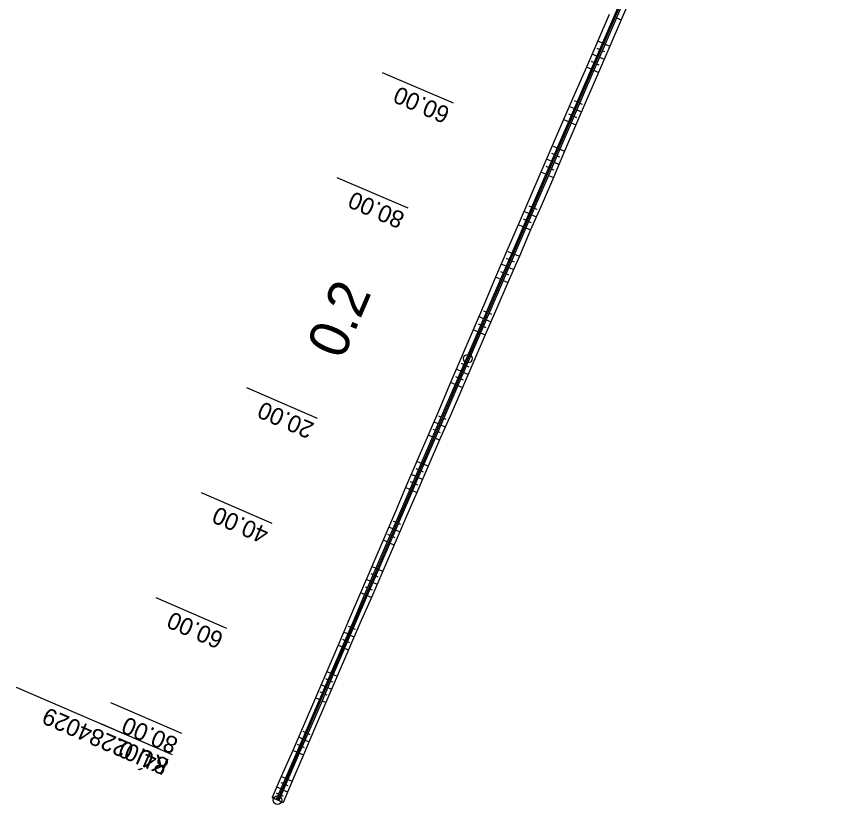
# Model space of a CAD drawing. Extents: x -481685 to -479315, y -1112639 to -1112242.
# Drawn here: x -480665.3 to -480519.8, y -1112634.9 to -1112497.2 of the extents above; entities that cross this region are included whole.
import ezdxf

# ---------------------------------------------------------------- set-up
doc = ezdxf.new("R2010")
doc.units = 0
for name, color, linetype in [('O6_HATCH_SLOPE_L', 7, 'Continuous'), ('O6_HATCH_SLOPE_R', 7, 'Continuous'), ('O6_HECTOMETRY', 7, 'Continuous'), ('O6_HLBODY', 7, 'Continuous'), ('O6_HRANA_TELESO', 7, 'Continuous'), ('O6_OSA', 7, 'Continuous'), ('O6_STANICENI', 7, 'Continuous'), ('O6_VOZOVKA', 7, 'Continuous'), ('O6_ZPEVKRAJ', 7, 'Continuous')]:
    doc.layers.add(name, color=color, linetype=linetype)

msp = doc.modelspace()

# ---------------------------------------------------------------- linework, layer by layer
at = {"layer": 'O6_HATCH_SLOPE_L'}
for p, q in [((-480560.38, -1112497.36), (-480559.57, -1112497.71)), ((-480562.86, -1112503.1), (-480562.45, -1112503.27)), ((-480562.04, -1112503.45), (-480562.04, -1112503.45)), ((-480563.35, -1112504.25), (-480562.53, -1112504.6)), ((-480564.34, -1112506.54), (-480563.52, -1112506.9)), ((-480563.85, -1112505.39), (-480563.43, -1112505.57)), ((-480563.02, -1112505.75), (-480563.02, -1112505.75)), ((-480566.82, -1112512.28), (-480566.4, -1112512.46)), ((-480567.31, -1112513.43), (-480566.48, -1112513.79)), ((-480565.98, -1112512.64), (-480565.98, -1112512.64)), ((-480567.81, -1112514.58), (-480567.39, -1112514.76)), ((-480566.97, -1112514.94), (-480566.97, -1112514.94)), ((-480568.3, -1112515.72), (-480567.46, -1112516.08)), ((-480571.27, -1112522.61), (-480570.42, -1112522.98)), ((-480570.78, -1112521.46), (-480570.35, -1112521.64)), ((-480569.93, -1112521.83), (-480569.93, -1112521.83)), ((-480571.77, -1112523.76), (-480571.34, -1112523.94)), ((-480570.92, -1112524.12), (-480570.92, -1112524.12)), ((-480572.26, -1112524.91), (-480571.41, -1112525.27)), ((-480574.74, -1112530.65), (-480574.31, -1112530.83)), ((-480573.89, -1112531.01), (-480573.89, -1112531.01)), ((-480575.73, -1112532.94), (-480575.3, -1112533.12)), ((-480575.23, -1112531.79), (-480574.38, -1112532.16)), ((-480576.22, -1112534.09), (-480575.38, -1112534.45)), ((-480574.88, -1112533.31), (-480574.88, -1112533.31)), ((-480578.7, -1112539.83), (-480578.28, -1112540.01)), ((-480577.86, -1112540.19), (-480577.86, -1112540.19)), ((-480579.19, -1112540.98), (-480578.35, -1112541.34)), ((-480579.69, -1112542.12), (-480579.27, -1112542.3)), ((-480578.85, -1112542.48), (-480578.85, -1112542.48)), ((-480580.18, -1112543.27), (-480579.35, -1112543.63)), ((-480583.15, -1112550.16), (-480582.33, -1112550.51)), ((-480582.66, -1112549.01), (-480582.25, -1112549.19)), ((-480581.83, -1112549.36), (-480581.83, -1112549.36)), ((-480583.65, -1112551.3), (-480583.24, -1112551.48)), ((-480582.83, -1112551.66), (-480582.83, -1112551.66)), ((-480584.14, -1112552.45), (-480583.33, -1112552.8)), ((-480586.62, -1112558.19), (-480586.22, -1112558.36)), ((-480585.82, -1112558.53), (-480585.82, -1112558.53)), ((-480587.61, -1112560.49), (-480587.21, -1112560.66)), ((-480587.11, -1112559.34), (-480586.32, -1112559.68)), ((-480588.1, -1112561.64), (-480587.32, -1112561.97)), ((-480586.82, -1112560.83), (-480586.82, -1112560.83)), ((-480590.58, -1112567.37), (-480590.2, -1112567.54)), ((-480589.81, -1112567.71), (-480589.81, -1112567.71)), ((-480591.07, -1112568.52), (-480590.31, -1112568.85)), ((-480591.57, -1112569.67), (-480591.19, -1112569.83)), ((-480590.81, -1112570), (-480590.81, -1112570)), ((-480592.06, -1112570.82), (-480591.31, -1112571.14)), ((-480594.54, -1112576.56), (-480594.17, -1112576.72)), ((-480595.03, -1112577.7), (-480594.29, -1112578.02)), ((-480593.8, -1112576.88), (-480593.8, -1112576.88)), ((-480595.53, -1112578.85), (-480595.16, -1112579.01)), ((-480594.79, -1112579.17), (-480594.79, -1112579.17)), ((-480596.02, -1112580), (-480595.29, -1112580.32)), ((-480598.5, -1112585.74), (-480598.14, -1112585.9)), ((-480597.77, -1112586.05), (-480597.77, -1112586.05)), ((-480599.49, -1112588.03), (-480599.13, -1112588.19)), ((-480598.99, -1112586.89), (-480598.27, -1112587.2)), ((-480599.98, -1112589.18), (-480599.27, -1112589.49)), ((-480598.77, -1112588.35), (-480598.77, -1112588.35)), ((-480602.46, -1112594.92), (-480602.1, -1112595.07)), ((-480601.75, -1112595.23), (-480601.75, -1112595.23)), ((-480602.95, -1112596.07), (-480602.25, -1112596.37)), ((-480603.94, -1112598.36), (-480603.24, -1112598.67)), ((-480603.45, -1112597.22), (-480603.1, -1112597.37)), ((-480602.74, -1112597.52), (-480602.74, -1112597.52)), ((-480606.42, -1112604.1), (-480606.07, -1112604.25)), ((-480606.92, -1112605.25), (-480606.23, -1112605.55)), ((-480605.73, -1112604.4), (-480605.73, -1112604.4)), ((-480607.41, -1112606.4), (-480607.07, -1112606.55)), ((-480606.72, -1112606.7), (-480606.72, -1112606.7)), ((-480607.91, -1112607.55), (-480607.22, -1112607.84)), ((-480610.88, -1112614.43), (-480610.2, -1112614.73)), ((-480610.38, -1112613.29), (-480610.04, -1112613.43)), ((-480609.71, -1112613.58), (-480609.71, -1112613.58)), ((-480611.37, -1112615.58), (-480611.03, -1112615.73)), ((-480610.7, -1112615.87), (-480610.7, -1112615.87)), ((-480611.86, -1112616.73), (-480611.19, -1112617.02)), ((-480614.34, -1112622.47), (-480613.99, -1112622.62)), ((-480613.65, -1112622.77), (-480613.65, -1112622.77)), ((-480614.84, -1112623.62), (-480614.14, -1112623.92)), ((-480615.83, -1112625.91), (-480615.12, -1112626.22)), ((-480615.33, -1112624.76), (-480614.98, -1112624.91)), ((-480614.63, -1112625.06), (-480614.63, -1112625.06)), ((-480618.2, -1112631.43), (-480617.84, -1112631.58)), ((-480617.48, -1112631.74), (-480617.48, -1112631.74)), ((-480619, -1112633.27), (-480618.64, -1112633.43)), ((-480618.6, -1112632.35), (-480617.88, -1112632.66)), ((-480619.4, -1112634.19), (-480618.67, -1112634.51)), ((-480618.27, -1112633.58), (-480618.27, -1112633.58))]:
    msp.add_line(p, q, dxfattribs=at)
at = {"layer": 'O6_HATCH_SLOPE_R'}
for p, q in [((-480563.83, -1112504.04), (-480564.65, -1112503.69)), ((-480564.15, -1112502.54), (-480564.15, -1112502.54)), ((-480563.33, -1112502.89), (-480563.74, -1112502.72)), ((-480565.15, -1112504.83), (-480565.15, -1112504.83)), ((-480564.32, -1112505.19), (-480564.73, -1112505.01)), ((-480564.82, -1112506.33), (-480565.64, -1112505.98)), ((-480568.13, -1112511.72), (-480568.13, -1112511.72)), ((-480567.29, -1112512.07), (-480567.71, -1112511.89)), ((-480569.12, -1112514.01), (-480569.12, -1112514.01)), ((-480567.79, -1112513.22), (-480568.62, -1112512.86)), ((-480568.78, -1112515.52), (-480569.62, -1112515.16)), ((-480568.28, -1112514.37), (-480568.7, -1112514.19)), ((-480572.1, -1112520.89), (-480572.1, -1112520.89)), ((-480571.25, -1112521.26), (-480571.68, -1112521.07)), ((-480571.75, -1112522.4), (-480572.6, -1112522.04)), ((-480573.09, -1112523.19), (-480573.09, -1112523.19)), ((-480572.24, -1112523.55), (-480572.67, -1112523.37)), ((-480572.74, -1112524.7), (-480573.59, -1112524.33)), ((-480575.71, -1112531.59), (-480576.56, -1112531.22)), ((-480576.07, -1112530.07), (-480576.07, -1112530.07)), ((-480575.22, -1112530.44), (-480575.64, -1112530.26)), ((-480577.05, -1112532.37), (-480577.05, -1112532.37)), ((-480576.21, -1112532.73), (-480576.63, -1112532.55)), ((-480576.7, -1112533.88), (-480577.55, -1112533.52)), ((-480580.02, -1112539.26), (-480580.02, -1112539.26)), ((-480579.17, -1112539.62), (-480579.6, -1112539.44)), ((-480581, -1112541.56), (-480581, -1112541.56)), ((-480579.67, -1112540.77), (-480580.51, -1112540.41)), ((-480580.66, -1112543.06), (-480581.5, -1112542.7)), ((-480580.17, -1112541.92), (-480580.58, -1112541.74)), ((-480583.96, -1112548.45), (-480583.96, -1112548.45)), ((-480583.14, -1112548.8), (-480583.55, -1112548.63)), ((-480583.63, -1112549.95), (-480584.45, -1112549.6)), ((-480584.94, -1112550.75), (-480584.94, -1112550.75)), ((-480584.12, -1112551.1), (-480584.53, -1112550.92)), ((-480584.62, -1112552.25), (-480585.43, -1112551.9)), ((-480587.89, -1112557.64), (-480587.89, -1112557.64)), ((-480587.59, -1112559.13), (-480588.38, -1112558.79)), ((-480587.1, -1112557.99), (-480587.49, -1112557.81)), ((-480588.88, -1112559.94), (-480588.88, -1112559.94)), ((-480588.09, -1112560.28), (-480588.48, -1112560.11)), ((-480588.58, -1112561.43), (-480589.37, -1112561.09)), ((-480591.82, -1112566.84), (-480591.82, -1112566.84)), ((-480591.06, -1112567.17), (-480591.44, -1112567)), ((-480592.81, -1112569.14), (-480592.81, -1112569.14)), ((-480592.05, -1112569.46), (-480592.43, -1112569.3)), ((-480591.55, -1112568.32), (-480592.31, -1112567.99)), ((-480592.54, -1112570.61), (-480593.3, -1112570.29)), ((-480595.76, -1112576.03), (-480595.76, -1112576.03)), ((-480595.02, -1112576.35), (-480595.39, -1112576.19)), ((-480595.51, -1112577.5), (-480596.25, -1112577.18)), ((-480596.5, -1112579.79), (-480597.24, -1112579.48)), ((-480596.75, -1112578.33), (-480596.75, -1112578.33)), ((-480596.01, -1112578.65), (-480596.38, -1112578.49)), ((-480599.7, -1112585.22), (-480599.7, -1112585.22)), ((-480599.47, -1112586.68), (-480600.2, -1112586.37)), ((-480598.98, -1112585.53), (-480599.34, -1112585.38)), ((-480600.69, -1112587.52), (-480600.69, -1112587.52)), ((-480599.97, -1112587.83), (-480600.33, -1112587.67)), ((-480600.46, -1112588.98), (-480601.18, -1112588.67)), ((-480603.65, -1112594.41), (-480603.65, -1112594.41)), ((-480602.94, -1112594.72), (-480603.29, -1112594.56)), ((-480604.63, -1112596.71), (-480604.63, -1112596.71)), ((-480603.93, -1112597.01), (-480604.28, -1112596.86)), ((-480603.43, -1112595.86), (-480604.14, -1112595.56)), ((-480604.42, -1112598.16), (-480605.13, -1112597.85)), ((-480607.59, -1112603.6), (-480607.59, -1112603.6)), ((-480606.9, -1112603.9), (-480607.24, -1112603.75)), ((-480607.39, -1112605.05), (-480608.08, -1112604.75)), ((-480608.38, -1112607.34), (-480609.07, -1112607.05)), ((-480608.58, -1112605.9), (-480608.58, -1112605.9)), ((-480607.89, -1112606.19), (-480608.23, -1112606.04)), ((-480611.53, -1112612.79), (-480611.53, -1112612.79)), ((-480610.86, -1112613.08), (-480611.19, -1112612.93)), ((-480611.35, -1112614.23), (-480612.02, -1112613.94)), ((-480612.52, -1112615.09), (-480612.52, -1112615.09)), ((-480611.85, -1112615.38), (-480612.18, -1112615.23)), ((-480612.34, -1112616.52), (-480613.01, -1112616.24)), ((-480615.31, -1112623.41), (-480615.99, -1112623.12)), ((-480615.49, -1112621.97), (-480615.49, -1112621.97)), ((-480614.82, -1112622.26), (-480615.16, -1112622.12)), ((-480616.49, -1112624.26), (-480616.49, -1112624.26)), ((-480615.81, -1112624.56), (-480616.15, -1112624.41)), ((-480616.3, -1112625.71), (-480616.99, -1112625.41)), ((-480619.08, -1112632.14), (-480619.79, -1112631.84)), ((-480619.39, -1112630.92), (-480619.39, -1112630.92)), ((-480618.68, -1112631.22), (-480619.03, -1112631.07)), ((-480620.19, -1112632.76), (-480620.19, -1112632.76)), ((-480619.48, -1112633.07), (-480619.83, -1112632.91)), ((-480619.88, -1112633.99), (-480620.59, -1112633.68))]:
    msp.add_line(p, q, dxfattribs=at)
at = {"layer": 'O6_HECTOMETRY'}
msp.add_circle((-480586.36, -1112556.94), 0.75, dxfattribs=at)
at = {"layer": 'O6_HLBODY'}
msp.add_line((-480638.01, -1112626.18), (-480665.28, -1112614.42), dxfattribs=at)
msp.add_circle((-480619.64, -1112634.1), 0.75, dxfattribs=at)
at = {"layer": 'O6_HRANA_TELESO'}
for p, q in [((-480557.6, -1112493.11), (-480559.57, -1112497.71)), ((-480561.67, -1112496.8), (-480563.66, -1112501.39)), ((-480559.57, -1112497.71), (-480561.54, -1112502.3)), ((-480563.66, -1112501.39), (-480565.64, -1112505.98)), ((-480561.54, -1112502.3), (-480563.52, -1112506.9)), ((-480565.64, -1112505.98), (-480567.63, -1112510.57)), ((-480563.52, -1112506.9), (-480565.49, -1112511.49)), ((-480567.63, -1112510.57), (-480569.62, -1112515.16)), ((-480565.49, -1112511.49), (-480567.46, -1112516.08)), ((-480569.62, -1112515.16), (-480571.6, -1112519.74)), ((-480567.46, -1112516.08), (-480569.44, -1112520.68)), ((-480571.6, -1112519.74), (-480573.59, -1112524.33)), ((-480569.44, -1112520.68), (-480571.41, -1112525.27)), ((-480573.59, -1112524.33), (-480575.57, -1112528.92)), ((-480571.41, -1112525.27), (-480573.39, -1112529.86)), ((-480575.57, -1112528.92), (-480577.55, -1112533.52)), ((-480573.39, -1112529.86), (-480575.38, -1112534.45)), ((-480577.55, -1112533.52), (-480579.52, -1112538.11)), ((-480575.38, -1112534.45), (-480577.36, -1112539.04)), ((-480579.52, -1112538.11), (-480581.5, -1112542.7)), ((-480577.36, -1112539.04), (-480579.35, -1112543.63)), ((-480581.5, -1112542.7), (-480583.47, -1112547.3)), ((-480579.35, -1112543.63), (-480581.34, -1112548.22)), ((-480583.47, -1112547.3), (-480585.43, -1112551.9)), ((-480581.34, -1112548.22), (-480583.33, -1112552.8)), ((-480585.43, -1112551.9), (-480587.4, -1112556.49)), ((-480583.33, -1112552.8), (-480585.32, -1112557.39)), ((-480587.4, -1112556.49), (-480589.37, -1112561.09)), ((-480585.32, -1112557.39), (-480587.32, -1112561.97)), ((-480589.37, -1112561.09), (-480591.33, -1112565.69)), ((-480587.32, -1112561.97), (-480589.31, -1112566.56)), ((-480591.33, -1112565.69), (-480593.3, -1112570.29)), ((-480589.31, -1112566.56), (-480591.31, -1112571.14)), ((-480593.3, -1112570.29), (-480595.27, -1112574.88)), ((-480591.31, -1112571.14), (-480593.3, -1112575.73)), ((-480595.27, -1112574.88), (-480597.24, -1112579.48)), ((-480593.3, -1112575.73), (-480595.29, -1112580.32)), ((-480597.24, -1112579.48), (-480599.21, -1112584.07)), ((-480595.29, -1112580.32), (-480597.28, -1112584.91)), ((-480599.21, -1112584.07), (-480601.18, -1112588.67)), ((-480597.28, -1112584.91), (-480599.27, -1112589.49)), ((-480601.18, -1112588.67), (-480603.15, -1112593.26)), ((-480599.27, -1112589.49), (-480601.25, -1112594.08)), ((-480603.15, -1112593.26), (-480605.13, -1112597.85)), ((-480601.25, -1112594.08), (-480603.24, -1112598.67)), ((-480605.13, -1112597.85), (-480607.1, -1112602.45)), ((-480603.24, -1112598.67), (-480605.23, -1112603.26)), ((-480607.1, -1112602.45), (-480609.07, -1112607.05)), ((-480605.23, -1112603.26), (-480607.22, -1112607.84)), ((-480609.07, -1112607.05), (-480611.04, -1112611.64)), ((-480607.22, -1112607.84), (-480609.21, -1112612.43)), ((-480611.04, -1112611.64), (-480613.01, -1112616.24)), ((-480609.21, -1112612.43), (-480611.19, -1112617.02)), ((-480613.01, -1112616.24), (-480615, -1112620.82)), ((-480611.19, -1112617.02), (-480613.16, -1112621.62)), ((-480615, -1112620.82), (-480616.99, -1112625.41)), ((-480613.16, -1112621.62), (-480615.12, -1112626.22)), ((-480616.99, -1112625.41), (-480618.99, -1112629.99)), ((-480615.12, -1112626.22), (-480617.09, -1112630.81)), ((-480618.99, -1112629.99), (-480620.59, -1112633.68)), ((-480617.09, -1112630.81), (-480618.67, -1112634.51))]:
    msp.add_line(p, q, dxfattribs=at)
at = {"layer": 'O6_OSA'}
msp.add_line((-480519.82, -1112402.65), (-480619.64, -1112634.1), dxfattribs=at)
at = {"layer": 'O6_STANICENI'}
for p, q in [((-480563.52, -1112501.45), (-480561.68, -1112502.24)), ((-480588.89, -1112512.29), (-480601.28, -1112506.95)), ((-480571.44, -1112519.82), (-480569.6, -1112520.61)), ((-480596.81, -1112530.66), (-480609.2, -1112525.31)), ((-480579.36, -1112538.18), (-480577.52, -1112538.97)), ((-480612.65, -1112567.39), (-480625.04, -1112562.04)), ((-480595.2, -1112574.91), (-480593.36, -1112575.7)), ((-480620.57, -1112585.75), (-480632.96, -1112580.4)), ((-480603.12, -1112593.27), (-480601.29, -1112594.07)), ((-480628.49, -1112604.11), (-480640.89, -1112598.77)), ((-480611.04, -1112611.64), (-480609.21, -1112612.43)), ((-480636.41, -1112622.48), (-480648.8, -1112617.13)), ((-480638, -1112626.17), (-480650.4, -1112620.82)), ((-480618.96, -1112630), (-480617.13, -1112630.8)), ((-480620.55, -1112633.7), (-480618.72, -1112634.49))]:
    msp.add_line(p, q, dxfattribs=at)
at = {"layer": 'O6_VOZOVKA'}
for p, q in [((-480558.87, -1112492.56), (-480560.85, -1112497.16)), ((-480558.41, -1112492.76), (-480560.39, -1112497.35)), ((-480560.85, -1112497.16), (-480562.83, -1112501.75)), ((-480560.39, -1112497.35), (-480562.37, -1112501.95)), ((-480562.83, -1112501.75), (-480564.81, -1112506.34)), ((-480562.37, -1112501.95), (-480564.35, -1112506.54)), ((-480564.81, -1112506.34), (-480566.79, -1112510.93)), ((-480564.35, -1112506.54), (-480566.33, -1112511.13)), ((-480566.79, -1112510.93), (-480568.77, -1112515.52)), ((-480566.33, -1112511.13), (-480568.31, -1112515.72)), ((-480568.77, -1112515.52), (-480570.75, -1112520.11)), ((-480568.31, -1112515.72), (-480570.29, -1112520.31)), ((-480570.75, -1112520.11), (-480572.73, -1112524.7)), ((-480570.29, -1112520.31), (-480572.27, -1112524.9)), ((-480572.73, -1112524.7), (-480574.71, -1112529.29)), ((-480572.27, -1112524.9), (-480574.25, -1112529.49)), ((-480574.71, -1112529.29), (-480576.69, -1112533.89)), ((-480574.25, -1112529.49), (-480576.23, -1112534.08)), ((-480576.69, -1112533.89), (-480578.67, -1112538.48)), ((-480576.23, -1112534.08), (-480578.21, -1112538.68)), ((-480578.67, -1112538.48), (-480580.65, -1112543.07)), ((-480578.21, -1112538.68), (-480580.19, -1112543.27)), ((-480580.65, -1112543.07), (-480582.63, -1112547.66)), ((-480580.19, -1112543.27), (-480582.17, -1112547.86)), ((-480582.63, -1112547.66), (-480584.61, -1112552.25)), ((-480582.17, -1112547.86), (-480584.15, -1112552.45)), ((-480584.61, -1112552.25), (-480586.59, -1112556.84)), ((-480584.15, -1112552.45), (-480586.13, -1112557.04)), ((-480586.59, -1112556.84), (-480588.57, -1112561.43)), ((-480586.13, -1112557.04), (-480588.11, -1112561.63)), ((-480588.57, -1112561.43), (-480590.55, -1112566.02)), ((-480588.11, -1112561.63), (-480590.09, -1112566.22)), ((-480590.55, -1112566.02), (-480592.53, -1112570.62)), ((-480590.09, -1112566.22), (-480592.07, -1112570.81)), ((-480592.53, -1112570.62), (-480594.51, -1112575.21)), ((-480592.07, -1112570.81), (-480594.05, -1112575.41)), ((-480594.51, -1112575.21), (-480596.49, -1112579.8)), ((-480594.05, -1112575.41), (-480596.03, -1112580)), ((-480596.49, -1112579.8), (-480598.47, -1112584.39)), ((-480596.03, -1112580), (-480598.01, -1112584.59)), ((-480598.47, -1112584.39), (-480600.45, -1112588.98)), ((-480598.01, -1112584.59), (-480599.99, -1112589.18)), ((-480600.45, -1112588.98), (-480602.43, -1112593.57)), ((-480599.99, -1112589.18), (-480601.97, -1112593.77)), ((-480602.43, -1112593.57), (-480604.41, -1112598.16)), ((-480601.97, -1112593.77), (-480603.95, -1112598.36)), ((-480604.41, -1112598.16), (-480606.39, -1112602.75)), ((-480603.95, -1112598.36), (-480605.93, -1112602.95)), ((-480606.39, -1112602.75), (-480608.37, -1112607.34)), ((-480605.93, -1112602.95), (-480607.91, -1112607.54)), ((-480608.37, -1112607.34), (-480610.35, -1112611.94)), ((-480607.91, -1112607.54), (-480609.89, -1112612.13)), ((-480610.35, -1112611.94), (-480612.33, -1112616.53)), ((-480609.89, -1112612.13), (-480611.87, -1112616.73)), ((-480612.33, -1112616.53), (-480614.31, -1112621.12)), ((-480611.87, -1112616.73), (-480613.85, -1112621.32)), ((-480614.31, -1112621.12), (-480616.29, -1112625.71)), ((-480613.85, -1112621.32), (-480615.84, -1112625.91)), ((-480616.29, -1112625.71), (-480618.27, -1112630.3)), ((-480615.84, -1112625.91), (-480617.82, -1112630.5)), ((-480618.27, -1112630.3), (-480619.87, -1112633.99)), ((-480617.82, -1112630.5), (-480619.41, -1112634.19))]:
    msp.add_line(p, q, dxfattribs=at)
at = {"layer": 'O6_ZPEVKRAJ'}
for p, q in [((-480558.87, -1112492.56), (-480560.85, -1112497.16)), ((-480558.41, -1112492.76), (-480560.39, -1112497.35)), ((-480560.85, -1112497.16), (-480562.83, -1112501.75)), ((-480560.39, -1112497.35), (-480562.37, -1112501.95)), ((-480562.83, -1112501.75), (-480564.81, -1112506.34)), ((-480562.37, -1112501.95), (-480564.35, -1112506.54)), ((-480564.81, -1112506.34), (-480566.79, -1112510.93)), ((-480564.35, -1112506.54), (-480566.33, -1112511.13)), ((-480566.79, -1112510.93), (-480568.77, -1112515.52)), ((-480566.33, -1112511.13), (-480568.31, -1112515.72)), ((-480568.77, -1112515.52), (-480570.75, -1112520.11)), ((-480568.31, -1112515.72), (-480570.29, -1112520.31)), ((-480570.75, -1112520.11), (-480572.73, -1112524.7)), ((-480570.29, -1112520.31), (-480572.27, -1112524.9)), ((-480572.73, -1112524.7), (-480574.71, -1112529.29)), ((-480572.27, -1112524.9), (-480574.25, -1112529.49)), ((-480574.71, -1112529.29), (-480576.69, -1112533.89)), ((-480574.25, -1112529.49), (-480576.23, -1112534.08)), ((-480576.69, -1112533.89), (-480578.67, -1112538.48)), ((-480576.23, -1112534.08), (-480578.21, -1112538.68)), ((-480578.67, -1112538.48), (-480580.65, -1112543.07)), ((-480578.21, -1112538.68), (-480580.19, -1112543.27)), ((-480580.65, -1112543.07), (-480582.63, -1112547.66)), ((-480580.19, -1112543.27), (-480582.17, -1112547.86)), ((-480582.63, -1112547.66), (-480584.61, -1112552.25)), ((-480582.17, -1112547.86), (-480584.15, -1112552.45)), ((-480584.61, -1112552.25), (-480586.59, -1112556.84)), ((-480584.15, -1112552.45), (-480586.13, -1112557.04)), ((-480586.59, -1112556.84), (-480588.57, -1112561.43)), ((-480586.13, -1112557.04), (-480588.11, -1112561.63)), ((-480588.57, -1112561.43), (-480590.55, -1112566.02)), ((-480588.11, -1112561.63), (-480590.09, -1112566.22)), ((-480590.55, -1112566.02), (-480592.53, -1112570.62)), ((-480590.09, -1112566.22), (-480592.07, -1112570.81)), ((-480592.53, -1112570.62), (-480594.51, -1112575.21)), ((-480592.07, -1112570.81), (-480594.05, -1112575.41)), ((-480594.51, -1112575.21), (-480596.49, -1112579.8)), ((-480594.05, -1112575.41), (-480596.03, -1112580)), ((-480596.49, -1112579.8), (-480598.47, -1112584.39)), ((-480596.03, -1112580), (-480598.01, -1112584.59)), ((-480598.47, -1112584.39), (-480600.45, -1112588.98)), ((-480598.01, -1112584.59), (-480599.99, -1112589.18)), ((-480600.45, -1112588.98), (-480602.43, -1112593.57)), ((-480599.99, -1112589.18), (-480601.97, -1112593.77)), ((-480602.43, -1112593.57), (-480604.41, -1112598.16)), ((-480601.97, -1112593.77), (-480603.95, -1112598.36)), ((-480604.41, -1112598.16), (-480606.39, -1112602.75)), ((-480603.95, -1112598.36), (-480605.93, -1112602.95)), ((-480606.39, -1112602.75), (-480608.37, -1112607.34)), ((-480605.93, -1112602.95), (-480607.91, -1112607.54)), ((-480608.37, -1112607.34), (-480610.35, -1112611.94)), ((-480607.91, -1112607.54), (-480609.89, -1112612.13)), ((-480610.35, -1112611.94), (-480612.33, -1112616.53)), ((-480609.89, -1112612.13), (-480611.87, -1112616.73)), ((-480612.33, -1112616.53), (-480614.31, -1112621.12)), ((-480611.87, -1112616.73), (-480613.85, -1112621.32)), ((-480614.31, -1112621.12), (-480616.29, -1112625.71)), ((-480613.85, -1112621.32), (-480615.84, -1112625.91)), ((-480616.29, -1112625.71), (-480618.27, -1112630.3)), ((-480615.84, -1112625.91), (-480617.82, -1112630.5)), ((-480618.27, -1112630.3), (-480619.87, -1112633.99)), ((-480617.82, -1112630.5), (-480619.41, -1112634.19))]:
    msp.add_line(p, q, dxfattribs=at)

# ---------------------------------------------------------------- texts
at = {"layer": 'O6_HECTOMETRY'}
msp.add_text('0.2', height=7, rotation=66.6242, dxfattribs=at).set_placement((-480608.31, -1112557.32))
at = {"layer": 'O6_HLBODY'}
msp.add_text('KÚ 0.284029', height=3, rotation=156.6698, dxfattribs=at).set_placement((-480638.4, -1112627.1))
at = {"layer": 'O6_STANICENI'}
for s, p in [('60.00', (-480589.28, -1112513.21)), ('80.00', (-480597.2, -1112531.57)), ('20.00', (-480613.04, -1112568.3)), ('40.00', (-480620.96, -1112586.67)), ('60.00', (-480628.88, -1112605.03)), ('80.00', (-480636.8, -1112623.4)), ('84.02', (-480638.4, -1112627.09))]:
    msp.add_text(s, height=2.999, rotation=156.6698, dxfattribs=at).set_placement(p)

doc.saveas('drawing.dxf')
